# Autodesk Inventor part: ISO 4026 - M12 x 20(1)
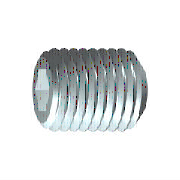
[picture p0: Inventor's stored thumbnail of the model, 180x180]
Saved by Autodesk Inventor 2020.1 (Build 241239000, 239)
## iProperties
Created: 2019-01
Part Number: ISO 4026 - M12 x 20(1)
Material: Edelstahl, 440C
Description: Innensechskant-Gewindestifte mit Kegelstumpf
Document SubType Name: Modeling
Standard: ISO 4026
Designer: lutzd
Standard Revision: Third edition 2003-12-01
Standards Organization: ISO
Language: de-DE
Size Designation: M12 x 20
Categories: <MemberInstance><Categories><Category DisplayName="Verbindungselemente" InternalName="e4da775c-781d-43d5-af7c-5136215cf5a6" Mnemonic="FSTN"><Category DisplayNam
Mass: 15.091 g
Surface Area: 11.0452 cm^2
Volume: 1.94723 cm^3
Density: 7.75 g/cm^3
Appearance: Halbpoliert
IsCustomPart: 0
Author: lutzd
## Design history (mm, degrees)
sketch "Skizze1"
  geometry: L1 (0, 0)-(10, 0); L2 (20, 3.464)-(20, 6); L3 (20, 6)-(0, 6); L4 (20, 3.464)-(12, 3.464); L5 (12, 3.464)-(10, 0); L6 (0, -1.2)-(0, 7.2) reference; L7 (0, 6)-(0, 0)
  constraints: 13 end point, 3 parallel, 1 collinear, 1 perpendicular, 1 point on line
  dimensions: "d0" = 8 distance of L2.start L4.end (= INTI); "d1" = 60 deg angle of L5 L1; "d2" = 12 diameter of L3 L1 (= NND); "d3" = 6.9282 diameter of L4 L1 (= 1.1547 x SW); "d5" = 20 distance from line of L2 L3.end (= NLG)
revolve "Körper" sketch "Skizze1" stored, may be unused: angle "d6" = 90 deg
sketch "Skizze2"
  geometry: L1 (-1.732, 3)-(1.732, 3); L2 (1.732, 3)-(3.464, 0); L3 (3.464, 0)-(1.732, -3); L4 (1.732, -3)-(-1.732, -3); L5 (-1.732, -3)-(-3.464, 0); L6 (-3.464, 0)-(-1.732, 3); A1 r 3.464 centre (0, 0) between (-1.732, 3) and (1.732, 3) reference; 2 further points
  constraints: 12 end point, 2 point on circle, 1 coincident, 1 horizontal, 11 other
extrude "Loch" join sketch "Skizze2" taper "d9" = 0 deg; stored distance "d21" = 10
workaxis "Work Axis1"
workplane "Work Plane1"
body "Solid1"
chamfer "Fase1" distance "d7" = 1.07354 (= -0.5 x GD1 + 0.5 x NND); stored, may be unused: angle "d8" = 45 deg (= FAWI), second distance "d29" = 1.07354 (= -0.5 x GD1 + 0.5 x NND)
feature "Gewinde" dims "d11" = 20 (= NLG), "d12" = 0
chamfer "Fase2" distance "d13" = 1.07354 (= -0.5 x GD1 + 0.5 x NND); stored, may be unused: angle "d14" = 45 deg (= FAWI), second distance "d30" = 1.07354 (= -0.5 x GD1 + 0.5 x NND)
other parameters: "NND" = 12 [user parameter; used in 5 equation terms], "NLG" = 20 [user parameter; used in 2 equation terms], "INTI" = 8 [user parameter; used in 1 equation term], "FAWI" = 45 deg [user parameter; used in 2 equation terms], "SW" = 6 [user parameter; used in 2 equation terms], "GD1" = 9.85293 (= THREADDIA - 1.2269 x PTC) [user parameter; used in 4 equation terms], "d4" = 0, "FAWI1" = 45 deg [user parameter], "d15" = 0, "d31" = 0, "GUL" = 1.07354 (= 0.61345 x PTC) [user parameter], "SPD" = 8.5 [user parameter], "SEWI" = 90 deg [user parameter], "TOA" = 30 deg [user parameter], "THREADDIA" = 12 [user parameter; used in 1 equation term], "TPU" = 5.71429 (computed from PTC) [user parameter], "PTC" = 1.75 [user parameter; used in 4 equation terms], "GAL" = 1.07354 (= 0.61345 x PTC) [user parameter], "E0" = 6.93 (= 1.155 x SW) [user parameter]
